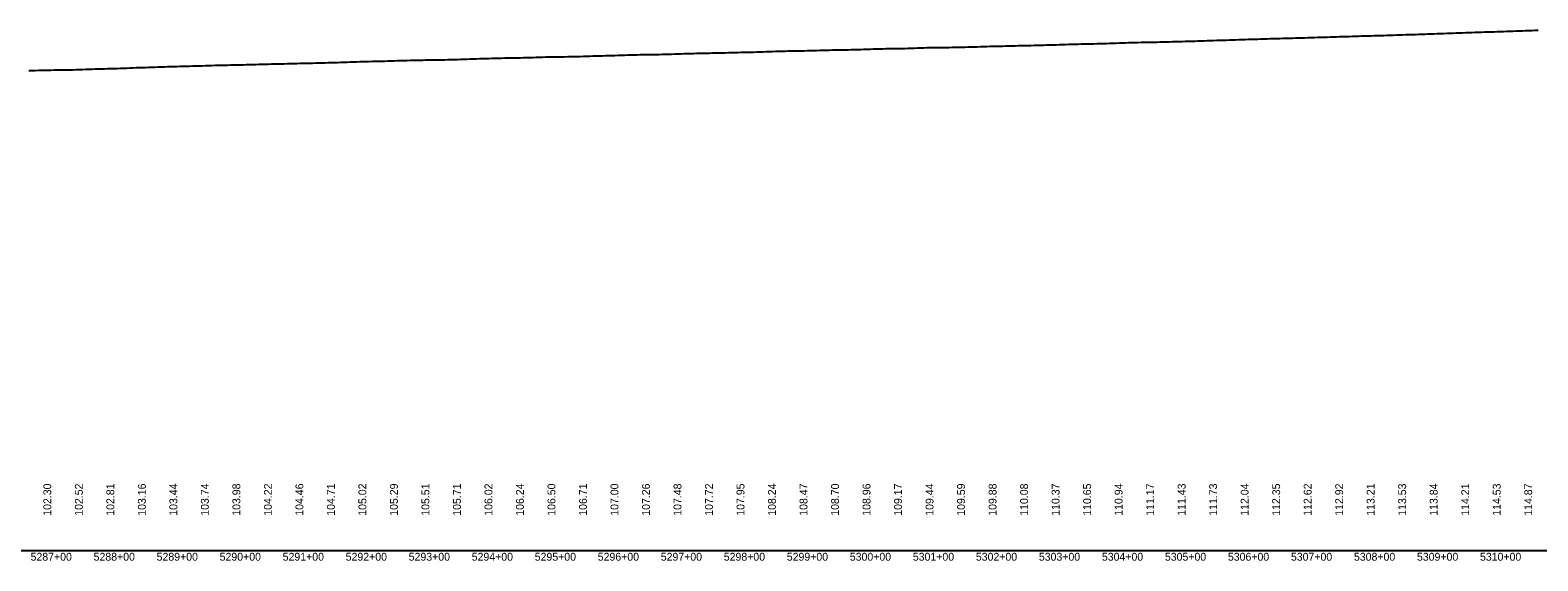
# Model space of a CAD drawing. Extents: x 2147288 to 2220488, y 740833 to 759333.
# Drawn here: x 2161047 to 2163439, y 742067 to 742908 of the extents above; entities that cross this region are included whole.
import ezdxf

# ---------------------------------------------------------------- set-up
doc = ezdxf.new("R2010")
doc.units = 0
for name, color, linetype in [('RD_DDB_Profile_EX', 7, 'Continuous'), ('RD_DDB_StaTX', 7, 'Continuous'), ('RD_DDB_StripGrade', 7, 'Continuous'), ('RD_GPK_Profile_Cell', 7, 'Continuous')]:
    doc.layers.add(name, color=color, linetype=linetype)

msp = doc.modelspace()

# ---------------------------------------------------------------- linework, layer by layer
at = {"layer": 'RD_DDB_Profile_EX'}
for points in [[(2163034.6, 742895.3), (2163039.6, 742895.2), (2163044.6, 742895.4), (2163049.6, 742895.6), (2163054.6, 742895.7), (2163059.6, 742895.8), (2163064.6, 742895.9), (2163069.6, 742896.1), (2163074.6, 742896.3), (2163079.6, 742896.5), (2163084.6, 742896.6), (2163089.6, 742896.8), (2163094.6, 742896.9), (2163099.6, 742897), (2163104.6, 742897.2), (2163109.6, 742897.4), (2163114.6, 742897.6), (2163119.6, 742897.7), (2163124.6, 742897.9), (2163129.6, 742898), (2163134.6, 742898.1), (2163139.6, 742898.3), (2163144.6, 742898.4), (2163149.6, 742898.6), (2163154.6, 742898.7), (2163159.6, 742898.9), (2163164.6, 742899), (2163169.6, 742899.2), (2163174.6, 742899.3), (2163179.6, 742899.4), (2163184.6, 742899.6), (2163189.6, 742899.7), (2163194.6, 742899.9), (2163199.6, 742900), (2163204.6, 742900.2), (2163209.6, 742900.4), (2163214.6, 742900.5), (2163219.6, 742900.7), (2163224.6, 742900.9), (2163229.6, 742901), (2163234.6, 742901.2), (2163239.6, 742901.3), (2163244.6, 742901.5), (2163249.6, 742901.6), (2163254.6, 742901.8), (2163259.6, 742902), (2163264.6, 742902.1), (2163269.6, 742902.3), (2163274.6, 742902.4), (2163279.6, 742902.6), (2163284.6, 742902.8), (2163289.6, 742903), (2163294.6, 742903.2), (2163299.6, 742903.3), (2163304.6, 742903.5), (2163309.6, 742903.7), (2163314.6, 742903.9), (2163319.6, 742904.1), (2163324.6, 742904.2), (2163329.6, 742904.4), (2163334.6, 742904.6), (2163339.6, 742904.8), (2163344.6, 742904.9), (2163349.6, 742905.1), (2163354.6, 742905.3), (2163359.6, 742905.4), (2163364.6, 742905.6), (2163369.6, 742905.7), (2163374.6, 742905.9), (2163379.6, 742906), (2163384.6, 742906.2), (2163389.6, 742906.3), (2163394.6, 742906.5), (2163399.6, 742906.7), (2163404.6, 742906.8), (2163409.6, 742907), (2163414.6, 742907.2), (2163419.6, 742907.4), (2163424.6, 742907.6), (2163429.6, 742907.7), (2163434.6, 742907.9), (2163439.6, 742908.1)], [(2162034.6, 742869.7), (2162039.6, 742869.8), (2162044.6, 742869.8), (2162049.6, 742869.9), (2162054.6, 742870), (2162059.6, 742870.2), (2162064.6, 742870.3), (2162069.6, 742870.6), (2162074.6, 742870.7), (2162079.6, 742870.8), (2162084.6, 742871), (2162089.6, 742871.1), (2162094.6, 742871.2), (2162099.6, 742871.3), (2162104.6, 742871.4), (2162109.6, 742871.5), (2162114.6, 742871.6), (2162119.6, 742871.7), (2162124.6, 742871.9), (2162129.6, 742872), (2162134.6, 742872.1), (2162139.6, 742872.2), (2162144.6, 742872.3), (2162149.6, 742872.4), (2162154.6, 742872.6), (2162159.6, 742872.7), (2162164.6, 742872.8), (2162169.6, 742872.9), (2162174.6, 742873), (2162179.6, 742873.1), (2162184.6, 742873.3), (2162189.6, 742873.4), (2162194.6, 742873.5), (2162199.6, 742873.7), (2162204.6, 742873.8), (2162209.6, 742874), (2162214.6, 742874.1), (2162219.6, 742874.3), (2162224.6, 742874.5), (2162229.6, 742874.6), (2162234.6, 742874.7), (2162239.6, 742874.8), (2162244.6, 742875), (2162249.6, 742875.1), (2162254.6, 742875.2), (2162259.6, 742875.3), (2162264.6, 742875.4), (2162269.6, 742875.5), (2162274.6, 742875.6), (2162279.6, 742875.7), (2162284.6, 742875.8), (2162289.6, 742876), (2162294.6, 742876.1), (2162299.6, 742876.2), (2162304.6, 742876.4), (2162309.6, 742876.5), (2162314.6, 742876.6), (2162319.6, 742876.7), (2162324.6, 742876.8), (2162329.6, 742876.9), (2162334.6, 742877), (2162339.6, 742877.1), (2162344.6, 742877.2), (2162349.6, 742877.3), (2162354.6, 742877.4), (2162359.6, 742877.5), (2162364.6, 742877.7), (2162369.6, 742877.9), (2162374.6, 742878), (2162379.6, 742878.2), (2162384.6, 742878.3), (2162389.6, 742878.5), (2162394.6, 742878.6), (2162399.6, 742878.7), (2162404.6, 742878.8), (2162409.6, 742878.9), (2162414.6, 742879), (2162419.6, 742879.1), (2162424.6, 742879.2), (2162429.6, 742879.2), (2162434.6, 742879.3), (2162439.6, 742879.5), (2162444.6, 742879.7), (2162449.6, 742879.8), (2162454.6, 742879.9), (2162459.6, 742880.1), (2162464.6, 742880.2), (2162469.6, 742880.4), (2162474.6, 742880.5), (2162479.6, 742880.6), (2162484.6, 742880.6), (2162489.6, 742880.8), (2162494.6, 742880.9), (2162499.6, 742880.8), (2162504.6, 742880.9), (2162509.6, 742881), (2162514.6, 742881.2), (2162519.6, 742881.3), (2162524.6, 742881.4), (2162529.6, 742881.3), (2162534.6, 742881.5)], [(2162534.6, 742881.5), (2162539.6, 742881.6), (2162544.6, 742881.7), (2162549.6, 742881.9), (2162554.6, 742882.1), (2162559.6, 742882.2), (2162564.6, 742882.3), (2162569.6, 742882.5), (2162574.6, 742882.7), (2162579.6, 742882.8), (2162584.6, 742882.9), (2162589.6, 742883), (2162594.6, 742883.2), (2162599.6, 742883.3), (2162604.6, 742883.4), (2162609.6, 742883.5), (2162614.6, 742883.6), (2162619.6, 742883.7), (2162624.6, 742883.7), (2162629.6, 742883.8), (2162634.6, 742883.9), (2162639.6, 742884.1), (2162644.6, 742884.2), (2162649.6, 742884.4), (2162654.6, 742884.5), (2162659.6, 742884.7), (2162664.6, 742884.8), (2162669.6, 742885), (2162674.6, 742885.1), (2162679.6, 742885.3), (2162684.6, 742885.4), (2162689.6, 742885.5), (2162694.6, 742885.7), (2162699.6, 742885.8), (2162704.6, 742886), (2162709.6, 742886.1), (2162714.6, 742886.3), (2162719.6, 742886.4), (2162724.6, 742886.5), (2162729.6, 742886.6), (2162734.6, 742886.7), (2162739.6, 742886.9), (2162744.6, 742887), (2162749.6, 742887.1), (2162754.6, 742887.2), (2162759.6, 742887.3), (2162764.6, 742887.5), (2162769.6, 742887.7), (2162774.6, 742887.9), (2162779.6, 742888.1), (2162784.6, 742888.2), (2162789.6, 742888.4), (2162794.6, 742888.6), (2162799.6, 742888.7), (2162804.6, 742888.8), (2162809.6, 742888.9), (2162814.6, 742889), (2162819.6, 742889.1), (2162824.6, 742889.2), (2162829.6, 742889.2), (2162834.6, 742889.3), (2162839.6, 742889.4), (2162844.6, 742889.6), (2162849.6, 742889.7), (2162854.6, 742889.8), (2162859.6, 742890), (2162864.6, 742890.1), (2162869.6, 742890.2), (2162874.6, 742890.3), (2162879.6, 742890.5), (2162884.6, 742890.7), (2162889.6, 742890.7), (2162894.6, 742890.9), (2162899.6, 742891), (2162904.6, 742891.2), (2162909.6, 742891.4), (2162914.6, 742891.6), (2162919.6, 742891.7), (2162924.6, 742891.9), (2162929.6, 742892), (2162934.6, 742892.2), (2162939.6, 742892.3), (2162944.6, 742892.4), (2162949.6, 742892.6), (2162954.6, 742892.7), (2162959.6, 742892.9), (2162964.6, 742893.1), (2162969.6, 742893.2), (2162974.6, 742893.4), (2162979.6, 742893.6), (2162984.6, 742893.7), (2162989.6, 742893.9), (2162994.6, 742894.1), (2162999.6, 742894.2), (2163004.6, 742894.3), (2163009.6, 742894.5), (2163014.6, 742894.7), (2163019.6, 742894.8), (2163024.6, 742895), (2163029.6, 742895.1), (2163034.6, 742895.3)], [(2161044.6, 742844), (2161049.6, 742844.2), (2161054.6, 742844.3), (2161059.6, 742844.5), (2161064.6, 742844.6), (2161069.6, 742844.7), (2161074.6, 742844.9), (2161079.6, 742844.9), (2161084.6, 742845.1), (2161089.6, 742845.3), (2161094.6, 742845.4), (2161099.6, 742845.4), (2161104.6, 742845.4), (2161109.6, 742845.4), (2161114.6, 742845.5), (2161119.6, 742845.7), (2161124.6, 742845.8), (2161129.6, 742846), (2161134.6, 742846.1), (2161139.6, 742846.3), (2161144.6, 742846.4), (2161149.6, 742846.6), (2161154.6, 742846.7), (2161159.6, 742846.8), (2161164.6, 742847), (2161169.6, 742847.1), (2161174.6, 742847.3), (2161179.6, 742847.4), (2161184.6, 742847.6), (2161189.6, 742847.7), (2161194.6, 742847.9), (2161199.6, 742848.1), (2161204.6, 742848.3), (2161209.6, 742848.5), (2161214.6, 742848.7), (2161219.6, 742848.8), (2161224.6, 742849), (2161229.6, 742849.2), (2161234.6, 742849.3), (2161239.6, 742849.4), (2161244.6, 742849.6), (2161249.6, 742849.8), (2161254.6, 742850), (2161259.6, 742850.1), (2161264.6, 742850.3), (2161269.6, 742850.4), (2161274.6, 742850.5), (2161279.6, 742850.6), (2161284.6, 742850.8), (2161289.6, 742850.9), (2161294.6, 742851.1), (2161299.6, 742851.2), (2161304.6, 742851.4), (2161309.6, 742851.5), (2161314.6, 742851.7), (2161319.6, 742851.8), (2161324.6, 742851.9), (2161329.6, 742852.1), (2161334.6, 742852.2), (2161339.6, 742852.4), (2161344.6, 742852.5), (2161349.6, 742852.7), (2161354.6, 742852.8), (2161359.6, 742852.9), (2161364.6, 742853), (2161369.6, 742853.1), (2161374.6, 742853.2), (2161379.6, 742853.3), (2161384.6, 742853.4), (2161389.6, 742853.5), (2161394.6, 742853.6), (2161399.6, 742853.7), (2161404.6, 742853.9), (2161409.6, 742854), (2161414.6, 742854.1), (2161419.6, 742854.2), (2161424.6, 742854.4), (2161429.6, 742854.5), (2161434.6, 742854.6), (2161439.6, 742854.7), (2161444.6, 742854.8), (2161449.6, 742854.9), (2161454.6, 742855.1), (2161459.6, 742855.2), (2161464.6, 742855.3), (2161469.6, 742855.4), (2161474.6, 742855.6), (2161479.6, 742855.7), (2161484.6, 742855.7), (2161489.6, 742855.8), (2161494.6, 742856), (2161499.6, 742856.1), (2161504.6, 742856.2), (2161509.6, 742856.4), (2161514.6, 742856.5), (2161519.6, 742856.7), (2161524.6, 742856.8), (2161529.6, 742856.9), (2161534.6, 742857.1)], [(2161534.6, 742857.1), (2161539.6, 742857.2), (2161544.6, 742857.3), (2161549.6, 742857.5), (2161554.6, 742857.7), (2161559.6, 742857.8), (2161564.6, 742858), (2161569.6, 742858.2), (2161574.6, 742858.3), (2161579.6, 742858.5), (2161584.6, 742858.6), (2161589.6, 742858.8), (2161594.6, 742858.9), (2161599.6, 742859), (2161604.6, 742859.1), (2161609.6, 742859.2), (2161614.6, 742859.4), (2161619.6, 742859.5), (2161624.6, 742859.7), (2161629.6, 742859.8), (2161634.6, 742860), (2161639.6, 742860.1), (2161644.6, 742860.2), (2161649.6, 742860.3), (2161654.6, 742860.4), (2161659.6, 742860.5), (2161664.6, 742860.6), (2161669.6, 742860.7), (2161674.6, 742860.9), (2161679.6, 742861), (2161684.6, 742861), (2161689.6, 742861.1), (2161694.6, 742861.2), (2161699.6, 742861.3), (2161704.6, 742861.3), (2161709.6, 742861.4), (2161714.6, 742861.5), (2161719.6, 742861.7), (2161724.6, 742861.8), (2161729.6, 742861.9), (2161734.6, 742862.1), (2161739.6, 742862.3), (2161744.6, 742862.5), (2161749.6, 742862.7), (2161754.6, 742862.9), (2161759.6, 742863), (2161764.6, 742863.1), (2161769.6, 742863.2), (2161774.6, 742863.4), (2161779.6, 742863.5), (2161784.6, 742863.6), (2161789.6, 742863.7), (2161794.6, 742863.8), (2161799.6, 742864), (2161804.6, 742864.1), (2161809.6, 742864.2), (2161814.6, 742864.3), (2161819.6, 742864.4), (2161824.6, 742864.5), (2161829.6, 742864.6), (2161834.6, 742864.7), (2161839.6, 742864.8), (2161844.6, 742865), (2161849.6, 742865.2), (2161854.6, 742865.3), (2161859.6, 742865.5), (2161864.6, 742865.6), (2161869.6, 742865.8), (2161874.6, 742865.8), (2161879.6, 742865.9), (2161884.6, 742866), (2161889.6, 742866), (2161894.6, 742866.1), (2161899.6, 742866.2), (2161904.6, 742866.3), (2161909.6, 742866.4), (2161914.6, 742866.5), (2161919.6, 742866.6), (2161924.6, 742866.8), (2161929.6, 742866.9), (2161934.6, 742867.1), (2161939.6, 742867.2), (2161944.6, 742867.3), (2161949.6, 742867.4), (2161954.6, 742867.6), (2161959.6, 742867.7), (2161964.6, 742867.9), (2161969.6, 742868.1), (2161974.6, 742868.2), (2161979.6, 742868.4), (2161984.6, 742868.5), (2161989.6, 742868.7), (2161994.6, 742868.8), (2161999.6, 742868.9), (2162004.6, 742869), (2162009.6, 742869.2), (2162014.6, 742869.4), (2162019.6, 742869.5), (2162024.6, 742869.7), (2162029.6, 742869.8), (2162034.6, 742869.7)]]:
    msp.add_lwpolyline(points, dxfattribs=at)
at = {"layer": 'RD_GPK_Profile_Cell'}
msp.add_line((2148888.3, 742083.4), (2165888.3, 742083.4), dxfattribs=at)

# ---------------------------------------------------------------- texts
at = {"layer": 'RD_DDB_StaTX'}
for s, p in [('5287+00', (2161047.3, 742067.2)), ('5288+00', (2161147.3, 742067.2)), ('5289+00', (2161247.3, 742067.2)), ('5290+00', (2161347.3, 742067.2)), ('5291+00', (2161447.3, 742067.2)), ('5292+00', (2161547.3, 742067.2)), ('5293+00', (2161647.3, 742067.2)), ('5294+00', (2161747.3, 742067.2)), ('5295+00', (2161847.3, 742067.2)), ('5296+00', (2161947.3, 742067.2)), ('5297+00', (2162047.3, 742067.2)), ('5298+00', (2162147.3, 742067.2)), ('5299+00', (2162247.3, 742067.2)), ('5300+00', (2162347.3, 742067.2)), ('5301+00', (2162447.3, 742067.2)), ('5302+00', (2162547.3, 742067.2)), ('5303+00', (2162647.3, 742067.2)), ('5304+00', (2162747.3, 742067.2)), ('5305+00', (2162847.3, 742067.2)), ('5306+00', (2162947.3, 742067.2)), ('5307+00', (2163047.3, 742067.2)), ('5308+00', (2163147.3, 742067.2)), ('5309+00', (2163247.3, 742067.2)), ('5310+00', (2163347.3, 742067.2))]:
    msp.add_text(s, height=12.5, dxfattribs=at).set_placement(p)
at = {"layer": 'RD_DDB_StripGrade'}
for s, p in [('102.30', (2161080.1, 742138.4)), ('102.52', (2161130.1, 742138.4)), ('102.81', (2161180.1, 742138.4)), ('103.16', (2161230.1, 742138.4)), ('103.44', (2161280.1, 742138.4)), ('103.74', (2161330.1, 742138.4)), ('103.98', (2161380.1, 742138.4)), ('104.22', (2161430.1, 742138.4)), ('104.46', (2161480.1, 742138.4)), ('104.71', (2161530.1, 742138.4)), ('105.02', (2161580.1, 742138.4)), ('105.29', (2161630.1, 742138.4)), ('105.51', (2161680.1, 742138.4)), ('105.71', (2161730.1, 742138.4)), ('106.02', (2161780.1, 742138.4)), ('106.24', (2161830.1, 742138.4)), ('106.50', (2161880.1, 742138.4)), ('106.71', (2161930.1, 742138.4)), ('107.00', (2161980.1, 742138.4)), ('107.26', (2162030.1, 742138.4)), ('107.48', (2162080.1, 742138.4)), ('107.72', (2162130.1, 742138.4)), ('107.95', (2162180.1, 742138.4)), ('108.24', (2162230.1, 742138.4)), ('108.47', (2162280.1, 742138.4)), ('108.70', (2162330.1, 742138.4)), ('108.96', (2162380.1, 742138.4)), ('109.17', (2162430.1, 742138.4)), ('109.44', (2162480.1, 742138.4)), ('109.59', (2162530.1, 742138.4)), ('109.88', (2162580.1, 742138.4)), ('110.08', (2162630.1, 742138.4)), ('110.37', (2162680.1, 742138.4)), ('110.65', (2162730.1, 742138.4)), ('110.94', (2162780.1, 742138.4)), ('111.17', (2162830.1, 742138.4)), ('111.43', (2162880.1, 742138.4)), ('111.73', (2162930.1, 742138.4)), ('112.04', (2162980.1, 742138.4)), ('112.35', (2163030.1, 742138.4)), ('112.62', (2163080.1, 742138.4)), ('112.92', (2163130.1, 742138.4)), ('113.21', (2163180.1, 742138.4)), ('113.53', (2163230.1, 742138.4)), ('113.84', (2163280.1, 742138.4)), ('114.21', (2163330.1, 742138.4)), ('114.53', (2163380.1, 742138.4)), ('114.87', (2163430.1, 742138.4))]:
    msp.add_text(s, height=12.5, rotation=90, dxfattribs=at).set_placement(p)

doc.saveas('drawing.dxf')
